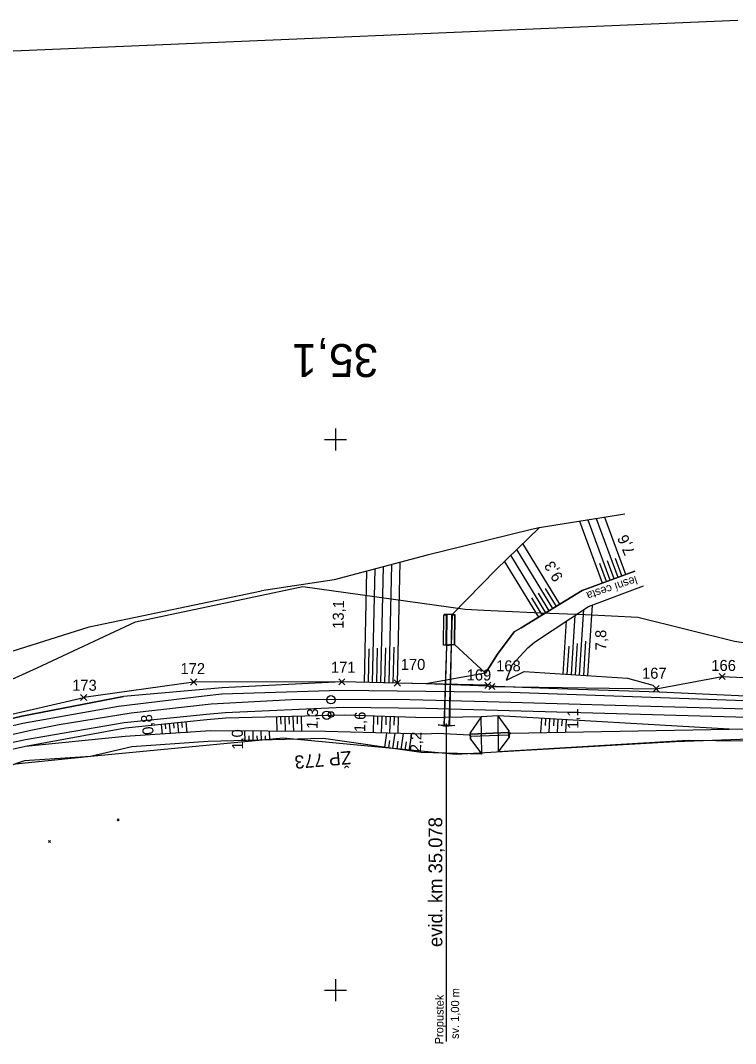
# Model space of a CAD drawing. Extents: x -806456 to -805395, y -1150847 to -1150506.
# Drawn here: x -805957.2 to -805827.3, y -1150709.7 to -1150523.9 of the extents above; entities that cross this region are included whole.
import ezdxf

# ---------------------------------------------------------------- set-up
doc = ezdxf.new("R2010")
doc.units = 0
for name, color, linetype in [('0381KM032-037P - Vrstva 1', 7, 'Continuous'), ('0381KM032-037P - Vrstva 19', 7, 'Continuous'), ('0381KM032-037P - Vrstva 4', 7, 'Continuous'), ('0381KM032-037P - Vrstva 48', 7, 'Continuous'), ('0381KM032-037P - Vrstva 49', 7, 'Continuous'), ('0381KM032-037P - Vrstva 51', 7, 'Continuous'), ('0381KM032-037P - Vrstva 7', 7, 'Continuous'), ('Default', 7, 'Continuous'), ('formát', 7, 'Continuous'), ('hran DP - hran DP', 7, 'Continuous'), ('krizky_1000 - Vrstva 1', 7, 'Continuous'), ('PSR_C2_2_Lomove_body_Vimperk - Vrstva 60', 7, 'Continuous'), ('PSR_C2_2_trasa_Vimperk - Kabelová trasa', 7, 'Continuous'), ('vyt_sit - stávající', 7, 'Continuous')]:
    doc.layers.add(name, color=color, linetype=linetype)

msp = doc.modelspace()

# ---------------------------------------------------------------- linework, layer by layer
at = {"layer": '0381KM032-037P - Vrstva 1'}
for points in [[(-805907.99, -1150647.29), (-805922.59, -1150648.1), (-805937.12, -1150649.71), (-805950.23, -1150651.85), (-805955.36, -1150652.84)], [(-805872.37, -1150647.65), (-805888.81, -1150647.23), (-805907.99, -1150647.29)], [(-805647.61, -1150654.06), (-805666.7, -1150653.55), (-805695.88, -1150652.69), (-805700.7, -1150652.54), (-805736.3, -1150651.55), (-805773.14, -1150650.48), (-805809.82, -1150649.4), (-805847.04, -1150648.36), (-805872.37, -1150647.65)], [(-805955.36, -1150652.84), (-805972.27, -1150656.66), (-805989.76, -1150661.17)]]:
    msp.add_lwpolyline(points, dxfattribs=at)
at = {"layer": '0381KM032-037P - Vrstva 19'}
for p, q in [((-805880.33, -1150637.33), (-805880.27, -1150631.9)), ((-805880.27, -1150631.9), (-805880.21, -1150631.81)), ((-805879.77, -1150631.9), (-805880.27, -1150631.9)), ((-805879.71, -1150631.81), (-805880.21, -1150631.81)), ((-805878.75, -1150631.78), (-805879.71, -1150631.81)), ((-805878.81, -1150631.82), (-805878.31, -1150631.82)), ((-805878.75, -1150631.78), (-805878.25, -1150631.78)), ((-805878.37, -1150637.24), (-805878.31, -1150631.82)), ((-805878.31, -1150631.82), (-805878.25, -1150631.78)), ((-805879.83, -1150637.33), (-805880.33, -1150637.33)), ((-805879.78, -1150637.42), (-805880.28, -1150652.07)), ((-805879.78, -1150637.42), (-805880.23, -1150651.86)), ((-805878.87, -1150637.24), (-805879.83, -1150637.33)), ((-805878.96, -1150637.32), (-805879.78, -1150637.42)), ((-805879.78, -1150637.42), (-805878.96, -1150637.32)), ((-805878.96, -1150637.32), (-805879.38, -1150652.05)), ((-805878.96, -1150637.32), (-805879.27, -1150651.81)), ((-805878.87, -1150637.24), (-805878.37, -1150637.24)), ((-805879.79, -1150709.36), (-805879.79, -1150651.59)), ((-805868.51, -1150653.23), (-805875.47, -1150653.52)), ((-805875.46, -1150653.52), (-805868.51, -1150653.23)), ((-805875.43, -1150653.86), (-805868.49, -1150653.67)), ((-805875.43, -1150653.87), (-805868.5, -1150653.67))]:
    msp.add_line(p, q, dxfattribs=at)
for points in [[(-805879.78, -1150637.42), (-805879.83, -1150637.33), (-805879.77, -1150631.9), (-805879.71, -1150631.81)], [(-805878.81, -1150631.82), (-805878.75, -1150631.78), (-805878.96, -1150637.32), (-805878.87, -1150637.24)], [(-805879.38, -1150652.05), (-805880.28, -1150652.07), (-805881.3, -1150651.8), (-805878.28, -1150651.94)]]:
    msp.add_lwpolyline(points, close=True, dxfattribs=at)
for points in [[(-805880.28, -1150652.07), (-805880.23, -1150651.86), (-805879.27, -1150651.81), (-805879.38, -1150652.05)], [(-805875.47, -1150653.27), (-805875.43, -1150654.45), (-805875.43, -1150653.87), (-805875.43, -1150653.86), (-805875.47, -1150653.52), (-805875.46, -1150653.52), (-805875.47, -1150653.27)], [(-805868.49, -1150652.87), (-805868.42, -1150654.14), (-805868.5, -1150653.67), (-805868.49, -1150653.67), (-805868.51, -1150653.23), (-805868.51, -1150653.23), (-805868.49, -1150652.87)]]:
    msp.add_lwpolyline(points, dxfattribs=at)
at = {"layer": '0381KM032-037P - Vrstva 4'}
for points in [[(-805734.36, -1150649.18), (-805786.14, -1150647.68), (-805826.72, -1150646.54), (-805841.05, -1150645.92), (-805859.62, -1150645.3), (-805883.54, -1150644.38), (-805898.84, -1150644.02), (-805920.59, -1150645.08)], [(-805920.59, -1150645.08), (-805938.49, -1150646.69), (-805957, -1150650.24), (-805973.18, -1150654.13), (-805996.94, -1150660.52), (-806010.57, -1150664.04), (-806045.29, -1150673.07), (-806070.44, -1150679.45), (-806076.44, -1150680.94), (-806080.95, -1150682.04), (-806094.16, -1150685.34), (-806107.83, -1150689.09)], [(-805687.98, -1150651.47), (-805728.71, -1150650.4), (-805771.75, -1150649.09), (-805796.82, -1150648.44), (-805827.25, -1150647.42), (-805868.08, -1150645.94), (-805883.57, -1150645.79), (-805899.1, -1150645.56), (-805920.66, -1150646.24), (-805923.83, -1150646.61)], [(-805923.83, -1150646.61), (-805939.39, -1150648.49), (-805956.78, -1150651.56), (-805972.77, -1150655.27), (-805996.74, -1150661.47), (-806010.38, -1150665.11), (-806045.15, -1150673.98), (-806070.28, -1150680.43), (-806094.02, -1150686.67), (-806107.78, -1150690.05)], [(-805688.15, -1150654.42), (-805728.36, -1150653.2), (-805771.94, -1150652.19), (-805796.53, -1150651.28), (-805827.23, -1150650.42), (-805883.58, -1150648.86), (-805898.54, -1150648.68), (-805920.02, -1150649.65), (-805923.42, -1150649.97)], [(-805923.37, -1150650.9), (-805938.15, -1150652.42), (-805956.35, -1150655.74), (-805972.37, -1150659.35), (-805995.12, -1150665.03), (-806009.04, -1150668.86), (-806027.1, -1150673.31), (-806034.62, -1150675.7), (-806043.91, -1150677.85), (-806068.97, -1150684.48)], [(-805923.42, -1150649.97), (-805938.4, -1150651.47), (-805956.35, -1150654.55), (-805972.44, -1150657.98), (-805995.68, -1150664.21)], [(-805687.42, -1150655.93), (-805728.29, -1150654.47), (-805772.22, -1150653.64), (-805796.51, -1150653.02), (-805828.44, -1150652.6), (-805870.39, -1150650.22), (-805873.51, -1150650.39), (-805883.54, -1150650.55), (-805898.37, -1150650.08), (-805919.92, -1150650.63), (-805923.37, -1150650.9)]]:
    msp.add_lwpolyline(points, dxfattribs=at)
at = {"layer": '0381KM032-037P - Vrstva 48'}
for p, q in [((-805850.02, -1150625.56), (-805854.06, -1150614.63)), ((-805848.61, -1150625.04), (-805852.55, -1150614.39)), ((-805847.21, -1150624.52), (-805851.04, -1150614.15)), ((-805851.43, -1150626.08), (-805855.57, -1150614.87)), ((-805860.47, -1150630.7), (-805867.02, -1150619.96)), ((-805859.19, -1150629.92), (-805865.92, -1150618.89)), ((-805861.75, -1150631.48), (-805868.13, -1150621.03)), ((-805847.91, -1150624.78), (-805849.08, -1150621.63)), ((-805894.73, -1150644.11), (-805894.25, -1150623.91)), ((-805893.23, -1150644.15), (-805892.74, -1150623.5)), ((-805891.73, -1150644.19), (-805891.23, -1150623.09)), ((-805890.23, -1150644.22), (-805889.72, -1150622.69)), ((-805888.73, -1150644.26), (-805888.21, -1150622.28)), ((-805863.03, -1150632.26), (-805869.23, -1150622.1)), ((-805850.72, -1150625.82), (-805851.95, -1150622.5)), ((-805849.32, -1150625.3), (-805850.51, -1150622.06)), ((-805859.83, -1150630.31), (-805861.82, -1150627.04)), ((-805862.39, -1150631.87), (-805864.28, -1150628.78)), ((-805861.11, -1150631.09), (-805863.05, -1150627.91)), ((-805855.59, -1150642.8), (-805854.83, -1150630.89)), ((-805854.09, -1150642.9), (-805853.28, -1150630.06)), ((-805858.59, -1150642.61), (-805857.97, -1150632.95)), ((-805857.09, -1150642.71), (-805856.4, -1150631.92)), ((-805854.84, -1150642.85), (-805854.45, -1150636.61)), ((-805893.98, -1150644.13), (-805893.83, -1150638)), ((-805892.48, -1150644.17), (-805892.33, -1150637.91)), ((-805890.98, -1150644.2), (-805890.83, -1150637.81)), ((-805889.48, -1150644.24), (-805889.33, -1150637.71)), ((-805857.84, -1150642.66), (-805857.51, -1150637.55)), ((-805856.34, -1150642.76), (-805855.98, -1150637.08)), ((-805931.69, -1150651.75), (-805931.5, -1150653.53)), ((-805930.94, -1150651.68), (-805930.85, -1150652.58)), ((-805930.19, -1150651.6), (-805930.01, -1150653.44)), ((-805929.45, -1150651.52), (-805929.35, -1150652.46)), ((-805928.7, -1150651.45), (-805928.51, -1150653.34)), ((-805927.96, -1150651.37), (-805927.86, -1150652.33)), ((-805927.21, -1150651.29), (-805927.01, -1150653.25)), ((-805910.7, -1150650.4), (-805910.63, -1150653.02)), ((-805909.95, -1150650.38), (-805909.92, -1150651.7)), ((-805909.2, -1150650.36), (-805909.13, -1150653.02)), ((-805908.45, -1150650.34), (-805908.42, -1150651.68)), ((-805907.7, -1150650.32), (-805907.63, -1150653.02)), ((-805906.95, -1150650.3), (-805906.92, -1150651.66)), ((-805906.2, -1150650.28), (-805906.13, -1150653.02)), ((-805893.06, -1150650.25), (-805893.15, -1150653.26)), ((-805892.31, -1150650.27), (-805892.35, -1150651.78)), ((-805891.56, -1150650.3), (-805891.65, -1150653.3)), ((-805890.81, -1150650.32), (-805890.85, -1150651.82)), ((-805890.06, -1150650.34), (-805890.15, -1150653.34)), ((-805889.31, -1150650.37), (-805889.35, -1150651.86)), ((-805888.56, -1150650.39), (-805888.65, -1150653.38)), ((-805862.55, -1150650.67), (-805862.69, -1150653.23)), ((-805861.8, -1150650.71), (-805861.87, -1150651.96)), ((-805861.05, -1150650.75), (-805861.19, -1150653.2)), ((-805860.3, -1150650.79), (-805860.37, -1150651.99)), ((-805859.55, -1150650.84), (-805859.69, -1150653.17)), ((-805858.8, -1150650.88), (-805858.87, -1150652.02)), ((-805858.06, -1150650.92), (-805858.18, -1150653.15)), ((-805916.42, -1150654.68), (-805916.46, -1150653.01)), ((-805914.92, -1150654.65), (-805914.96, -1150653.01)), ((-805913.42, -1150654.61), (-805913.46, -1150653.01)), ((-805911.92, -1150654.57), (-805911.96, -1150653.01)), ((-805891.01, -1150655.91), (-805890.65, -1150653.33)), ((-805889.53, -1150656.12), (-805889.14, -1150653.37)), ((-805888.04, -1150656.33), (-805887.63, -1150653.41)), ((-805886.56, -1150656.54), (-805886.12, -1150653.45)), ((-805915.67, -1150654.66), (-805915.69, -1150653.84)), ((-805914.17, -1150654.63), (-805914.19, -1150653.82)), ((-805912.67, -1150654.59), (-805912.69, -1150653.8)), ((-805890.27, -1150656.01), (-805890.08, -1150654.68)), ((-805888.79, -1150656.22), (-805888.58, -1150654.8)), ((-805887.3, -1150656.44), (-805887.09, -1150654.93))]:
    msp.add_line(p, q, dxfattribs=at)
at = {"layer": '0381KM032-037P - Vrstva 49'}
for p, q in [((-805883.54, -1150644.38), (-805898.84, -1150644.02)), ((-805873.4, -1150657.16), (-805873.51, -1150650.39)), ((-805868.18, -1150653.33), (-805828.44, -1150652.6)), ((-805939.34, -1150668.9), (-805939.69, -1150669.26)), ((-805939.69, -1150668.9), (-805939.34, -1150669.25)), ((-805952.13, -1150672.84), (-805951.77, -1150673.19)), ((-805951.77, -1150672.84), (-805952.12, -1150673.19))]:
    msp.add_line(p, q, dxfattribs=at)
for points in [[(-805847.37, -1150613.56), (-805862.98, -1150616.05), (-805864.35, -1150616.33), (-805883.33, -1150620.98), (-805900.2, -1150625.5), (-805913.4, -1150627.48)], [(-805862.98, -1150616.05), (-805870.78, -1150623.59), (-805878.75, -1150631.78)], [(-805845.56, -1150623.91), (-805855.14, -1150627.45), (-805866.22, -1150634.21), (-805867.47, -1150634.93), (-805870.51, -1150638.97), (-805872.7, -1150642.46)], [(-805973.62, -1150650.67), (-805958.72, -1150638.45), (-805944.76, -1150634.02), (-805913.4, -1150627.48)], [(-805868.9, -1150643.71), (-805867.89, -1150640.94), (-805864.99, -1150637.81), (-805863.82, -1150636.79), (-805853.97, -1150630.32), (-805843.97, -1150626.57)], [(-805878.75, -1150631.78), (-805878.25, -1150631.78), (-805878.31, -1150631.82), (-805878.37, -1150637.24), (-805872.7, -1150642.46)], [(-805872.7, -1150642.46), (-805883.54, -1150644.38)], [(-805868.9, -1150643.71), (-805865.69, -1150642.16), (-805846.9, -1150643.36)], [(-805883.54, -1150644.38), (-805898.84, -1150644.02), (-805920.59, -1150645.08)], [(-805846.9, -1150643.36), (-805842.28, -1150644.6), (-805841.05, -1150645.92)], [(-805920.59, -1150645.08), (-805938.49, -1150646.69)], [(-805786.14, -1150647.68), (-805826.72, -1150646.54), (-805841.05, -1150645.92)], [(-806076.44, -1150680.94), (-806070.44, -1150679.45), (-806045.29, -1150673.07), (-806010.57, -1150664.04), (-805996.94, -1150660.52), (-805973.18, -1150654.13), (-805957, -1150650.24), (-805938.49, -1150646.69)], [(-805923.37, -1150650.9), (-805938.15, -1150652.42), (-805956.35, -1150655.74), (-805972.37, -1150659.35), (-805995.12, -1150665.03)], [(-805873.51, -1150650.39), (-805883.54, -1150650.55), (-805898.37, -1150650.08), (-805919.92, -1150650.63), (-805923.37, -1150650.9)], [(-805873.51, -1150650.39), (-805875.47, -1150653.27), (-805875.46, -1150653.52), (-805875.59, -1150653.71)], [(-805687.42, -1150655.93), (-805728.29, -1150654.47), (-805772.22, -1150653.64), (-805796.51, -1150653.02), (-805828.44, -1150652.6), (-805870.39, -1150650.22)], [(-805687.58, -1150660.02), (-805738.95, -1150663.31), (-805774.06, -1150657.65), (-805795.8, -1150655.14), (-805835.84, -1150654.7), (-805870.36, -1150656.71), (-805870.39, -1150650.22)], [(-805870.36, -1150656.71), (-805868.42, -1150654.14), (-805868.5, -1150653.67), (-805868.18, -1150653.33), (-805868.51, -1150653.23), (-805868.49, -1150652.87), (-805870.39, -1150650.22)], [(-805922.71, -1150652.93), (-805938.23, -1150653.94), (-805956.35, -1150655.74)], [(-805875.59, -1150653.71), (-805881.41, -1150653.41), (-805883.63, -1150653.51), (-805901.81, -1150653.03), (-805922.71, -1150652.93)], [(-805923.15, -1150654.86), (-805936.98, -1150655.81), (-805944.5, -1150657.57), (-805956.52, -1150658.37), (-805958.13, -1150658.91), (-805970.8, -1150664), (-805994.63, -1150670.19)], [(-805873.4, -1150657.16), (-805884.43, -1150656.84), (-805902.18, -1150654.32), (-805923.15, -1150654.86)], [(-805875.59, -1150653.71), (-805875.43, -1150653.87), (-805875.43, -1150654.45), (-805873.4, -1150657.16)]]:
    msp.add_lwpolyline(points, dxfattribs=at)
at = {"layer": '0381KM032-037P - Vrstva 51'}
for points in [[(-805872.7, -1150642.46), (-805870.51, -1150638.97), (-805867.47, -1150634.93), (-805866.22, -1150634.21), (-805855.14, -1150627.45), (-805845.56, -1150623.91)], [(-805867.47, -1150634.93), (-805866.22, -1150634.21), (-805855.14, -1150627.45), (-805845.56, -1150623.91)], [(-805864.99, -1150637.81), (-805863.82, -1150636.79), (-805853.97, -1150630.32), (-805843.97, -1150626.57)], [(-805872.7, -1150642.46), (-805870.51, -1150638.97), (-805867.47, -1150634.93)], [(-805868.9, -1150643.71), (-805867.89, -1150640.94), (-805864.99, -1150637.81)]]:
    msp.add_lwpolyline(points, dxfattribs=at)
at = {"layer": '0381KM032-037P - Vrstva 7'}
msp.add_line((-805900.84, -1150649.94), (-805900.74, -1150649.94), dxfattribs=at)
for centre, radius in [((-805900.8, -1150647.27), 0.75), ((-805900.79, -1150649.94), 0.5)]:
    msp.add_circle(centre, radius, dxfattribs=at)
at = {"layer": 'formát'}
msp.add_line((-805826.83, -1150523.88), (-806456.26, -1150550.6), dxfattribs=at)
at = {"layer": 'hran DP - hran DP'}
for p, q in [((-805936.34, -1150633.1), (-805905.92, -1150626.68)), ((-805905.92, -1150626.68), (-805876.4, -1150630.84)), ((-805876.4, -1150630.84), (-805873.01, -1150630.99)), ((-805873.01, -1150630.99), (-805862.56, -1150631.46)), ((-805954.21, -1150641.47), (-805936.34, -1150633.1)), ((-805862.56, -1150631.46), (-805854.6, -1150631.81)), ((-805854.6, -1150631.81), (-805845.04, -1150632.24)), ((-805845.04, -1150632.24), (-805827.46, -1150636.65)), ((-805827.46, -1150636.65), (-805818.65, -1150637.92)), ((-805984.31, -1150655.05), (-805954.21, -1150641.47)), ((-805909.49, -1150654.26), (-805944.43, -1150657.58)), ((-805878.04, -1150657.24), (-805909.49, -1150654.26)), ((-805838.22, -1150654.94), (-805878.04, -1150657.24)), ((-805807.41, -1150653.77), (-805838.22, -1150654.94)), ((-805944.43, -1150657.58), (-805958.14, -1150658.97))]:
    msp.add_line(p, q, dxfattribs=at)
at = {"layer": 'krizky_1000 - Vrstva 1'}
for points in [[(-805900, -1150598), (-805900, -1150602)], [(-805902, -1150600), (-805898, -1150600)], [(-805900, -1150698), (-805900, -1150702)], [(-805902, -1150700), (-805898, -1150700)]]:
    msp.add_lwpolyline(points, dxfattribs=at)
at = {"layer": 'PSR_C2_2_Lomove_body_Vimperk - Vrstva 60'}
for p, q in [((-805926.31, -1150644.6), (-805925.21, -1150643.5)), ((-805925.21, -1150644.6), (-805926.31, -1150643.5)), ((-805899.39, -1150644.57), (-805898.29, -1150643.47)), ((-805898.29, -1150644.57), (-805899.39, -1150643.47)), ((-805889.28, -1150644.78), (-805888.18, -1150643.68)), ((-805888.18, -1150644.78), (-805889.28, -1150643.68)), ((-805872.84, -1150645.2), (-805871.74, -1150644.1)), ((-805871.74, -1150645.2), (-805872.84, -1150644.1)), ((-805872.13, -1150645.39), (-805871.03, -1150644.29)), ((-805871.03, -1150645.39), (-805872.13, -1150644.29)), ((-805830.24, -1150643.62), (-805829.14, -1150642.52)), ((-805829.14, -1150643.62), (-805830.24, -1150642.52)), ((-805842.22, -1150645.81), (-805841.12, -1150644.71)), ((-805841.12, -1150645.81), (-805842.22, -1150644.71)), ((-805946.3, -1150647.43), (-805945.2, -1150646.33)), ((-805945.2, -1150647.43), (-805946.3, -1150646.33))]:
    msp.add_line(p, q, dxfattribs=at)
at = {"layer": 'PSR_C2_2_trasa_Vimperk - Kabelová trasa'}
for p, q in [((-805925.76, -1150644.05), (-805945.75, -1150646.88)), ((-805872.29, -1150644.65), (-805888.73, -1150644.23)), ((-805984.72, -1150655.91), (-805945.75, -1150646.88))]:
    msp.add_line(p, q, dxfattribs=at)
for points in [[(-805888.73, -1150644.23), (-805898.84, -1150644.02), (-805925.76, -1150644.05)], [(-805871.58, -1150644.84), (-805841.67, -1150645.26), (-805829.69, -1150643.07), (-805746.23, -1150646.95), (-805734.34, -1150648.12), (-805727.43, -1150648.58), (-805708.99, -1150648.44)]]:
    msp.add_lwpolyline(points, dxfattribs=at)
at = {"layer": 'vyt_sit - stávající'}
msp.add_line((-805901.64, -1150650.08), (-805901.54, -1150650.08), dxfattribs=at)
msp.add_circle((-805901.58, -1150650.08), 0.756, dxfattribs=at)

# ---------------------------------------------------------------- texts
at = {"layer": '0381KM032-037P - Vrstva 19'}
for s, height, rotation, p in [('evid. km 35,078', 2.5, 90.0485, (-805880.55, -1150692.19)), ('sv. 1,00 m', 1.5, 89.3778, (-805877.56, -1150708.91)), (' Propustek', 1.5, 89.2433, (-805880.41, -1150710.44))]:
    msp.add_text(s, height=height, rotation=rotation, dxfattribs=at).set_placement(p)
at = {"layer": '0381KM032-037P - Vrstva 48'}
for s, rotation, p in [('7,6', 113.3216, (-805845.52, -1150620.49)), ('9,3', 121.2221, (-805858.53, -1150625.04)), ('13,1', 88.6293, (-805898.52, -1150634.39)), ('7,8', 90.583, (-805850.73, -1150638.27)), ('1,3', 88.4218, (-805903.23, -1150652.58)), ('1,6', 88.4623, (-805894.58, -1150653.18)), ('1,1', 90.4951, (-805855.82, -1150652.56)), ('0,8', 95.8667, (-805933, -1150653.53)), ('1,0', 91.4666, (-805916.75, -1150656.32)), ('2,2', 88.3753, (-805884.43, -1150656.84))]:
    msp.add_text(s, height=2, rotation=rotation, dxfattribs=at).set_placement(p)
at = {"layer": '0381KM032-037P - Vrstva 51'}
msp.add_text('lesní cesta', height=1.5, rotation=198.6145, dxfattribs=at).set_placement((-805845.41, -1150624.74))
at = {"layer": '0381KM032-037P - Vrstva 7'}
msp.add_text('35,1', height=6, rotation=180, dxfattribs=at).set_placement((-805892.22, -1150582.65))
at = {"layer": 'Default'}
for s, p in [('172', (-805928.15, -1150642.61)), ('171', (-805900.8, -1150642.37)), ('170', (-805888.11, -1150641.86)), ('168', (-805870.77, -1150642.11)), ('166', (-805831.65, -1150642.04)), ('169', (-805876.13, -1150643.77)), ('167', (-805844.25, -1150643.45)), ('173', (-805947.84, -1150645.64))]:
    msp.add_text(s, height=2, dxfattribs=at).set_placement(p)
at = {"layer": 'vyt_sit - stávající'}
msp.add_text('ŽP 773', height=2.4, rotation=185, dxfattribs=at).set_placement((-805897.19, -1150656.55))

doc.saveas('drawing.dxf')
